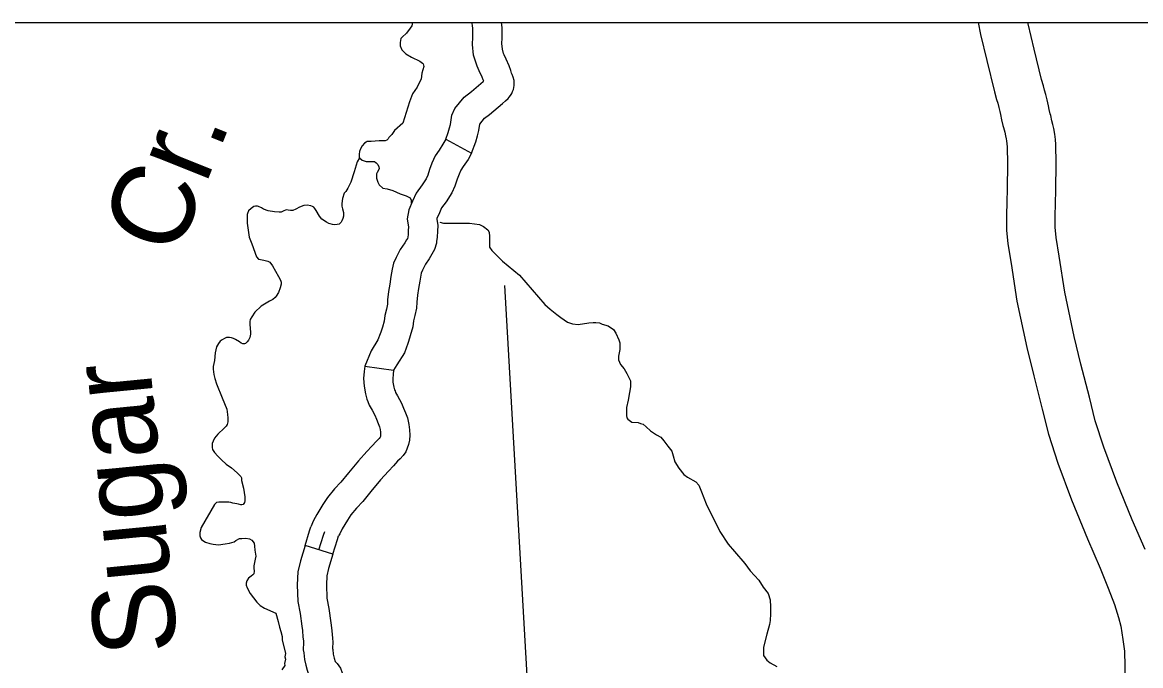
# Model space of a CAD drawing. Extents: x 1720274 to 1751788, y 372074 to 391887.
# Drawn here: x 1732023 to 1732931, y 381294 to 381816 of the extents above; entities that cross this region are included whole.
import ezdxf

# ---------------------------------------------------------------- set-up
doc = ezdxf.new("R2010")
doc.units = 0
for name, color, linetype in [('Level 10', 7, 'Continuous'), ('Level 35', 7, 'Continuous'), ('Level 45', 7, 'Continuous'), ('Level 5', 7, 'Continuous'), ('R_Draft', 7, 'Continuous')]:
    doc.layers.add(name, color=color, linetype=linetype)

msp = doc.modelspace()

# ---------------------------------------------------------------- linework, layer by layer
at = {"layer": 'Level 10'}
for points in [[(1732799.17, 381816.11), (1732801.06, 381806.37), (1732806.2, 381785.09), (1732812.46, 381759.64), (1732814.15, 381753.6), (1732815.09, 381750.38), (1732815.99, 381747.04), (1732816.92, 381743.81), (1732817.46, 381741.21), (1732818.16, 381737), (1732819.34, 381732.46), (1732819.74, 381730.75), (1732820.72, 381727.04), (1732821.36, 381724.11), (1732822.01, 381721.6), (1732822.29, 381719.98), (1732822.51, 381717.62), (1732822.72, 381714.92), (1732823.14, 381701.2), (1732822.82, 381680.98), (1732822.47, 381670.18), (1732822.07, 381659.5), (1732822.29, 381647.43), (1732823.4, 381636.36), (1732825.88, 381620.28), (1732830.71, 381589.76), (1732838.67, 381552.27), (1732844.29, 381529.11), (1732851.18, 381502.15), (1732856.32, 381481.78), (1732863.92, 381458.24), (1732874.94, 381428.36), (1732887.89, 381396.83), (1732898.19, 381373.02), (1732904.73, 381356.74), (1732909.83, 381343.54), (1732913.23, 381332.89), (1732914.92, 381326.03), (1732916.75, 381315.02), (1732917.92, 381305.55), (1732918.65, 381281.63)], [(1732934.65, 381388.22), (1732924.29, 381412.17), (1732911.75, 381442.7), (1732901.26, 381471.15), (1732894.31, 381492.68), (1732889.47, 381511.88), (1732882.62, 381538.66), (1732877.19, 381561.03), (1732869.57, 381596.95), (1732864.91, 381626.38), (1732862.6, 381641.35), (1732861.75, 381649.76), (1732861.59, 381659.12), (1732861.95, 381668.81), (1732862.31, 381680.03), (1732862.64, 381701.49), (1732862.17, 381717.02), (1732861.88, 381720.95), (1732861.48, 381725.21), (1732860.65, 381729.96), (1732859.79, 381733.28), (1732859.13, 381736.29), (1732858.06, 381740.36), (1732857.68, 381741.97), (1732856.84, 381745.23), (1732856.29, 381748.46), (1732855.3, 381753.27), (1732854.04, 381757.65), (1732853.11, 381761.11), (1732852.12, 381764.48), (1732850.67, 381769.67), (1732844.58, 381794.44), (1732839.67, 381814.79), (1732839.41, 381816.11)]]:
    msp.add_lwpolyline(points, dxfattribs=at)
at = {"layer": 'Level 35'}
for points in [[(1732339.96, 381816.11), (1732339.6, 381813.42), (1732338.18, 381811.52), (1732335.1, 381807.24), (1732331.54, 381804.16), (1732330.59, 381802.97), (1732330.11, 381799.88), (1732330.11, 381797.03), (1732331.3, 381793.71), (1732334.62, 381790.62), (1732339.13, 381787.77), (1732346.01, 381784.49), (1732348.13, 381783.08), (1732348.69, 381782.38), (1732349.12, 381780.25), (1732347.56, 381774.89), (1732347.14, 381769.95), (1732345.17, 381766.56), (1732343.85, 381763.44), (1732339.89, 381758.16), (1732337.69, 381751.55), (1732332.15, 381734.32)], [(1732332.15, 381734.32), (1732325.34, 381728.31), (1732323.15, 381724.96), (1732320.83, 381722.5), (1732320.18, 381721.47), (1732319.15, 381720.57), (1732317.74, 381720.05), (1732315.29, 381719.92), (1732312.97, 381719.8), (1732309.74, 381719.67), (1732306.39, 381719.41), (1732303.17, 381719.28), (1732302.27, 381718.89), (1732301.11, 381717.99), (1732299.05, 381715.92), (1732297.76, 381713.47), (1732296.98, 381711.28), (1732296.6, 381709.09), (1732296.6, 381708.18), (1732296.6, 381707.02), (1732296.98, 381706.25), (1732299.05, 381704.31), (1732300.85, 381703.67), (1732302.53, 381703.28), (1732305.23, 381703.28), (1732307.42, 381703.28), (1732309.05, 381703.04), (1732310.52, 381702.12), (1732311.99, 381700.58), (1732312.71, 381698.77), (1732312.84, 381697.48), (1732312.34, 381696.21)], [(1732296.98, 381706.25), (1732295.06, 381702.8), (1732292.66, 381694.87), (1732289.84, 381686.3), (1732287.45, 381681.4), (1732285.78, 381678.78), (1732284.63, 381677.32), (1732283.06, 381673.04), (1732282.65, 381668.97), (1732282.75, 381666.78), (1732283.17, 381664.69), (1732284, 381661.76), (1732284, 381660.51), (1732283.9, 381658.84), (1732283.38, 381656.86), (1732282.75, 381654.87), (1732282.23, 381653.93), (1732281.29, 381653.1), (1732280.35, 381652.37), (1732278.79, 381651.95), (1732276.7, 381651.84), (1732275.03, 381651.95), (1732273.15, 381652.47), (1732272, 381652.89), (1732270.23, 381653.83), (1732266.37, 381656.44), (1732264.49, 381658.74), (1732261.68, 381663.33), (1732260.63, 381665.11), (1732259.8, 381665.94), (1732258.75, 381666.67), (1732257.61, 381667.09), (1732254.37, 381667.61), (1732251.76, 381667.4), (1732248.22, 381666.05), (1732245.19, 381664.37), (1732242.79, 381663.33), (1732241.02, 381663.33), (1732239.14, 381663.75), (1732238.1, 381663.85), (1732236.95, 381663.54), (1732235.49, 381663.23), (1732233.51, 381662.08), (1732231.84, 381661.97), (1732227.98, 381662.18), (1732222.87, 381663.12), (1732219.11, 381664.48), (1732217.34, 381665.52), (1732215.04, 381666.67), (1732214.21, 381666.99), (1732212.64, 381666.99), (1732211.18, 381666.67), (1732208.99, 381665.11), (1732207.01, 381663.02), (1732205.97, 381661.03), (1732205.86, 381660.09), (1732205.86, 381658.32), (1732205.76, 381652.99), (1732207.53, 381641.61), (1732209.51, 381636.29), (1732213.48, 381625.63), (1732214.94, 381623.96), (1732216.61, 381623.55), (1732219.42, 381623.13), (1732222.55, 381622.29), (1732224.12, 381621.35), (1732226.41, 381618.32), (1732231.21, 381609.66), (1732232.78, 381606.84), (1732233.3, 381605.06), (1732233.4, 381603.5), (1732232.67, 381600.47), (1732231.11, 381596.71), (1732229.33, 381593.89), (1732228.5, 381592.64), (1732226.62, 381591.17), (1732224.01, 381589.71), (1732217.23, 381585.64), (1732212.12, 381580.94), (1732209.72, 381577.08), (1732208.26, 381574.89), (1732207.95, 381573.32), (1732207.84, 381571.13), (1732208.16, 381567.47), (1732208.47, 381564.55), (1732208.47, 381562.98), (1732207.95, 381560.37), (1732207.01, 381558.18), (1732205.86, 381556.61), (1732204.5, 381555.46), (1732203.67, 381555.15), (1732202.31, 381555.15), (1732200.85, 381555.78), (1732199.5, 381556.61), (1732196.37, 381558.6), (1732194.8, 381559.54), (1732193.03, 381560.06), (1732191.57, 381560.27), (1732190, 381560.27), (1732189.06, 381560.16), (1732187.29, 381559.43)], [(1732312.34, 381696.21), (1732311.4, 381694.3), (1732310.89, 381693.01), (1732310.89, 381689.68), (1732311.84, 381686.36), (1732313.03, 381684.22), (1732315.88, 381681.61), (1732319.43, 381680.89), (1732323.94, 381679.47), (1732329.88, 381676.86), (1732334.86, 381675.19), (1732338.18, 381673.53), (1732338.89, 381671.87), (1732338.89, 381669.24)], [(1732362.1, 381653.93), (1732365.23, 381653.11), (1732375.91, 381653.11), (1732386.35, 381653.11), (1732394.42, 381651.92), (1732397.74, 381650.26), (1732401.06, 381647.64), (1732402.25, 381645.74), (1732402.48, 381642.18), (1732402.48, 381639.57), (1732402.48, 381636.24), (1732402.48, 381633.63), (1732404.38, 381631.02), (1732413.16, 381622.23), (1732426.93, 381610.83), (1732447.33, 381587.08), (1732451.84, 381583.28), (1732457.06, 381579.01), (1732460.38, 381576.39), (1732465.84, 381572.83), (1732469.87, 381571.41), (1732474.38, 381570.93), (1732483.16, 381572.12), (1732486.72, 381572.36), (1732488.86, 381572.36), (1732491.7, 381572.12), (1732494.08, 381571.17), (1732498.82, 381569.74), (1732503.09, 381566.89), (1732504.99, 381563.81), (1732507.6, 381558.34), (1732508.31, 381555.97), (1732508.31, 381550.51), (1732507.37, 381545.04), (1732507.37, 381542.19)], [(1732187.29, 381559.43), (1732185.62, 381558.39), (1732183.95, 381557.24), (1732182.49, 381555.46), (1732181.03, 381552.75), (1732179.88, 381547.74), (1732179.15, 381541.47), (1732178.32, 381536.77), (1732178.32, 381534.47), (1732178.84, 381530.19), (1732179.47, 381526.85), (1732181.03, 381522.57), (1732185.41, 381511.4), (1732189.27, 381502.1), (1732189.79, 381497.82), (1732190.11, 381495), (1732190, 381491.77), (1732189.48, 381489.57), (1732188.75, 381488.32), (1732187.08, 381486.65), (1732182.07, 381481.74), (1732179.36, 381478.5), (1732178.11, 381476), (1732177.48, 381474.33), (1732177.38, 381472.45), (1732177.38, 381471.09), (1732177.59, 381469.42), (1732179.15, 381466.91), (1732181.97, 381463.99), (1732184.89, 381460.96), (1732188.75, 381457.41), (1732193.03, 381454.38), (1732197.72, 381450.31), (1732199.5, 381448.53), (1732200.64, 381447.28), (1732201.27, 381446.24), (1732201.27, 381445.61), (1732201.27, 381444.15), (1732202.73, 381437.99), (1732203.77, 381430.89), (1732203.88, 381427.55), (1732203.57, 381426.4), (1732203.15, 381425.46), (1732202.42, 381424.73), (1732201.48, 381424.41), (1732200.54, 381424.41), (1732198.66, 381424.83), (1732197.51, 381425.14), (1732195.74, 381425.46), (1732194.28, 381425.88), (1732192.61, 381426.29), (1732191.05, 381426.5), (1732188.86, 381426.61), (1732186.87, 381426.61), (1732186.35, 381426.61), (1732184.79, 381426.61), (1732182.8, 381426.5), (1732180.93, 381426.19), (1732179.36, 381424.62), (1732168.51, 381406.03), (1732167.47, 381402.07), (1732167.47, 381401.13), (1732167.36, 381399.14), (1732167.89, 381397.68), (1732168.82, 381396.32), (1732169.76, 381395.49), (1732172.06, 381394.03), (1732175.61, 381393.09), (1732178.21, 381392.36), (1732182.49, 381391.94), (1732187.92, 381392.88), (1732191.57, 381393.3), (1732195.2, 381394.42), (1732196.52, 381395.33), (1732199.45, 381396.95), (1732201.48, 381397.15), (1732204.61, 381397.36), (1732207.65, 381396.75), (1732209.47, 381395.74), (1732211.39, 381393.31), (1732211.8, 381390.98), (1732212.1, 381387.53), (1732212.71, 381382.77), (1732212.41, 381380.24), (1732211.19, 381374.87), (1732211.19, 381373.05), (1732211.49, 381370.52), (1732211.29, 381368.49), (1732210.48, 381367.48), (1732208.96, 381366.37), (1732206.94, 381364.95), (1732205.42, 381362.82), (1732204.92, 381360.69), (1732205.02, 381359.28), (1732205.93, 381356.95), (1732208.36, 381352.49), (1732213.72, 381345.5), (1732216.45, 381342.77), (1732219.99, 381340.44), (1732229.2, 381336.59), (1732231.07, 381329.57)], [(1732507.37, 381542.19), (1732508.79, 381538.39), (1732511.87, 381534.83), (1732514.01, 381531.03), (1732516.86, 381525.09), (1732517.09, 381522.24), (1732516.86, 381520.34), (1732516.15, 381515.59), (1732515.2, 381509.42), (1732513.77, 381503.48), (1732513.77, 381499.21), (1732513.77, 381496.83), (1732514.01, 381494.93), (1732514.72, 381493.98), (1732518.04, 381491.61), (1732523.26, 381491.13), (1732525.16, 381490.42), (1732527.3, 381489.94), (1732529.67, 381487.81), (1732533.23, 381484.48), (1732537.98, 381481.16), (1732541.53, 381479.26), (1732543.91, 381476.41), (1732547.23, 381472.13), (1732550.55, 381468.09), (1732551.74, 381464.29), (1732552.92, 381459.31), (1732556.25, 381454.08), (1732560.28, 381449.09), (1732563.37, 381446.96), (1732570.01, 381443.16), (1732572.38, 381440.31), (1732574.52, 381435.08), (1732578.31, 381425.34), (1732589.47, 381402.78), (1732596.35, 381392.57), (1732601.33, 381386.63), (1732609.87, 381376.89), (1732614.14, 381370.96), (1732621.03, 381363.36), (1732624.59, 381357.66), (1732628.86, 381352.43), (1732630.28, 381347.21), (1732630.75, 381341.51), (1732630.52, 381335.81), (1732630.28, 381330.58), (1732629.81, 381327.26), (1732627.67, 381319.42), (1732624.82, 381308.73), (1732624.82, 381304.93), (1732625.06, 381302.08), (1732627.67, 381298.28), (1732630.28, 381296.14), (1732635.74, 381293.29)], [(1732231.07, 381329.57), (1732232.03, 381325.15), (1732233.18, 381321.7), (1732234.14, 381317.48), (1732234.33, 381314.79), (1732236.82, 381303.85), (1732236.44, 381300.97), (1732236.88, 381298.99), (1732236.24, 381295.59), (1732236.39, 381293.95), (1732234.06, 381290.51)]]:
    msp.add_lwpolyline(points, dxfattribs=at)
at = {"layer": 'Level 45'}
for p, q in [((1732367.05, 381721.28), (1732387.86, 381709.94)), ((1732301.22, 381536.92), (1732324.7, 381533.69)), ((1732275.36, 381384.39), (1732252.75, 381391.49))]:
    msp.add_line(p, q, dxfattribs=at)
for points in [[(1732392.59, 381780.62), (1732391.64, 381782.92), (1732389.65, 381789.51), (1732388.68, 381798.11), (1732388.99, 381803.97), (1732388.99, 381810.79), (1732388.7, 381813.83), (1732388.19, 381816.11)], [(1732414.49, 381789.68), (1732413.99, 381790.89), (1732412.96, 381794.31), (1732412.45, 381798.82), (1732412.69, 381803.33), (1732412.69, 381811.93), (1732412.29, 381816.11)], [(1732387.86, 381709.94), (1732391.37, 381719.17), (1732392.78, 381723.87), (1732393.99, 381728.37), (1732394.73, 381733.58), (1732398.51, 381738.3), (1732402.6, 381741.37), (1732413.18, 381750.19), (1732415.46, 381752.31), (1732417.55, 381754.29), (1732418.57, 381755.38), (1732419.64, 381756.78), (1732420.55, 381758.27), (1732421.31, 381759.85), (1732421.9, 381761.5), (1732422.33, 381763.2), (1732422.57, 381764.93), (1732422.64, 381766.68), (1732422.5, 381768.86), (1732421.85, 381771.52), (1732420.97, 381773.66), (1732420.5, 381774.99), (1732419.9, 381777.01), (1732418.46, 381780.86), (1732415.92, 381786.23), (1732414.49, 381789.68)], [(1732367.05, 381721.28), (1732368.86, 381726.64), (1732369.98, 381730.35), (1732370.73, 381733.14), (1732371.83, 381740.88), (1732374.4, 381746.11), (1732381.89, 381755.46), (1732387.89, 381759.96), (1732397.5, 381767.97), (1732397.79, 381768.24), (1732397.43, 381769.44), (1732396.61, 381771.63), (1732394.24, 381776.64), (1732392.59, 381780.62)], [(1732367.05, 381721.28), (1732364.76, 381717.09), (1732361.61, 381712.29), (1732358.52, 381707.83), (1732355.81, 381701.67), (1732353.94, 381696.52), (1732352.42, 381691.97), (1732351.1, 381689.13), (1732347.86, 381684.15), (1732342.88, 381677.56), (1732340.12, 381671.01), (1732336.92, 381663.92), (1732335.6, 381656.52), (1732336.71, 381649.82), (1732336.62, 381647.5), (1732336.5, 381643.99), (1732336.16, 381641.81)], [(1732387.86, 381709.94), (1732385.1, 381704.89), (1732381.26, 381699.04), (1732379.3, 381696.2), (1732377.81, 381692.83), (1732376.32, 381688.73), (1732374.48, 381683.19), (1732371.88, 381677.61), (1732367.27, 381670.53), (1732363.57, 381665.63), (1732361.85, 381661.53), (1732359.73, 381656.85), (1732359.65, 381656.39), (1732360.49, 381651.31), (1732360.3, 381646.63), (1732360.14, 381641.72), (1732359.56, 381638.07)], [(1732336.16, 381641.85), (1732335.87, 381640.77), (1732335.24, 381639.63), (1732333.76, 381637.13), (1732329.94, 381631.78), (1732326.84, 381625.25), (1732324.65, 381620.68), (1732323.39, 381615.62), (1732322.48, 381609.69), (1732321.48, 381603.69), (1732320.6, 381597.68), (1732319.85, 381590.91), (1732319.6, 381587.19), (1732318.81, 381583.14), (1732317.63, 381578.25), (1732316.95, 381573.65), (1732315.56, 381568.53), (1732314.2, 381564.54)], [(1732359.56, 381638.07), (1732359.36, 381636.85), (1732357.98, 381631.77), (1732355.81, 381627.86), (1732353.64, 381624.19), (1732350.45, 381619.72), (1732348.23, 381615.04), (1732347.06, 381612.6), (1732346.65, 381610.94), (1732345.88, 381605.93), (1732344.89, 381600.04), (1732344.11, 381594.67), (1732343.46, 381588.82), (1732343.15, 381584.13), (1732341.98, 381578.09), (1732340.92, 381573.73), (1732340.2, 381568.79), (1732338.23, 381561.58), (1732336.63, 381556.88)], [(1732314.2, 381564.54), (1732313.76, 381563.24), (1732311.99, 381558.38), (1732306.36, 381549.47), (1732301.22, 381536.92)], [(1732336.63, 381556.88), (1732336.11, 381555.37), (1732333.39, 381547.89), (1732327.27, 381538.2), (1732324.7, 381533.69)], [(1732301.22, 381536.92), (1732300.65, 381532.79), (1732300.13, 381527.08), (1732300.66, 381520.83), (1732301.8, 381514.47), (1732303.07, 381510.12), (1732303.77, 381508.38), (1732304.9, 381505.36), (1732307.28, 381501.38), (1732309.49, 381497.19), (1732310.74, 381494), (1732312.22, 381490.37), (1732313.22, 381487.87), (1732313.79, 381485.51), (1732314.05, 381483.33), (1732314.14, 381481.04), (1732314.09, 381480.13), (1732314.05, 381479.93), (1732313.84, 381479.35), (1732312.82, 381478.25), (1732310.74, 381476.18), (1732306.98, 381472), (1732303.03, 381467.69)], [(1732324.7, 381533.69), (1732324.2, 381530.1), (1732323.92, 381527.01), (1732324.18, 381523.94), (1732324.91, 381519.9), (1732325.5, 381517.85), (1732325.87, 381516.93), (1732326.34, 381515.69), (1732327.95, 381513), (1732331.07, 381507.07), (1732332.75, 381502.8), (1732334.2, 381499.23), (1732335.86, 381495.08), (1732337.15, 381489.71), (1732337.69, 381485.22), (1732337.87, 381480.85), (1732337.65, 381476.97), (1732336.89, 381473.44), (1732335.8, 381470.37), (1732334.48, 381467.46), (1732332.44, 381464.55), (1732329.87, 381461.79), (1732327.95, 381459.87), (1732324.52, 381456.05), (1732320.48, 381451.66)], [(1732303.03, 381467.69), (1732296.18, 381460.24), (1732287.97, 381450.37), (1732281.82, 381442.81), (1732276.62, 381437.33), (1732270.94, 381430.31), (1732267.09, 381424.61), (1732262.38, 381416.43), (1732259.72, 381411.58), (1732257.49, 381406.52)], [(1732320.48, 381451.66), (1732314.03, 381444.63), (1732306.27, 381435.31), (1732299.63, 381427.15), (1732294.45, 381421.7), (1732290.02, 381416.2), (1732287.21, 381412.04), (1732283.04, 381404.81), (1732280.91, 381400.94), (1732280.05, 381399.24)], [(1732252.75, 381391.49), (1732256.47, 381403.36), (1732257.49, 381406.52)], [(1732264.05, 381387.94), (1732267.76, 381399.76), (1732268.77, 381402.88)], [(1732275.36, 381384.39), (1732279.06, 381396.17), (1732280.05, 381399.24)], [(1732252.75, 381391.49), (1732249.01, 381378.97), (1732246.84, 381369.89), (1732246.46, 381359.41), (1732246.91, 381346.04), (1732248.82, 381336.25), (1732250.3, 381325.94), (1732250.59, 381322.5), (1732251.1, 381317), (1732251.45, 381313.98), (1732251.52, 381312.68), (1732251.39, 381306.76), (1732251.69, 381304.24)], [(1732275.36, 381384.39), (1732271.91, 381372.82), (1732270.43, 381366.66), (1732270.17, 381359.38), (1732270.53, 381348.72), (1732272.19, 381340.2), (1732273.85, 381328.63), (1732274.2, 381324.6), (1732274.67, 381319.45), (1732275.07, 381316.03), (1732275.24, 381313.11), (1732275.12, 381307.89), (1732275.23, 381307.01)], [(1732251.69, 381304.24), (1732252.31, 381298.96), (1732253.42, 381294.3), (1732254.48, 381290.25), (1732256.12, 381285.51), (1732259.72, 381281.02), (1732259.95, 381280.8), (1732259.87, 381278.33), (1732259.87, 381278.29), (1732257.29, 381273.48), (1732253.18, 381266.2), (1732250.86, 381249.87), (1732248.8, 381243.07), (1732247.12, 381227.88)], [(1732275.23, 381307.01), (1732275.69, 381303.1), (1732276.41, 381300.06), (1732277.17, 381297.18), (1732278.79, 381295.69), (1732281.6, 381291.82), (1732282.8, 381287.95), (1732283.65, 381284.09), (1732283.65, 381280.47), (1732283.5, 381275.42), (1732282.32, 381270.01), (1732278.05, 381262.05), (1732276.01, 381258.45), (1732274.07, 381244.74), (1732272.12, 381238.29), (1732270.67, 381225.27)]]:
    msp.add_lwpolyline(points, dxfattribs=at)
at = {"layer": 'Level 5'}
msp.add_lwpolyline([(1732414.67, 381602.56), (1732434.09, 381262.05)], dxfattribs=at)
at = {"layer": 'R_Draft'}
msp.add_lwpolyline([(1729990.7, 381816.11), (1741847.55, 381816.11), (1741847.55, 374371.32), (1729990.7, 374371.32)], close=True, dxfattribs=at)

# ---------------------------------------------------------------- texts
at = {"layer": 'Level 35'}
for s, rotation, p in [('Cr.', 68.16358, (1732148.1, 381623.87)), ('Sugar', 95.58071, (1732149.81, 381305.64))]:
    msp.add_text(s, height=66.739, rotation=rotation, dxfattribs=at).set_placement(p)

doc.saveas('drawing.dxf')
